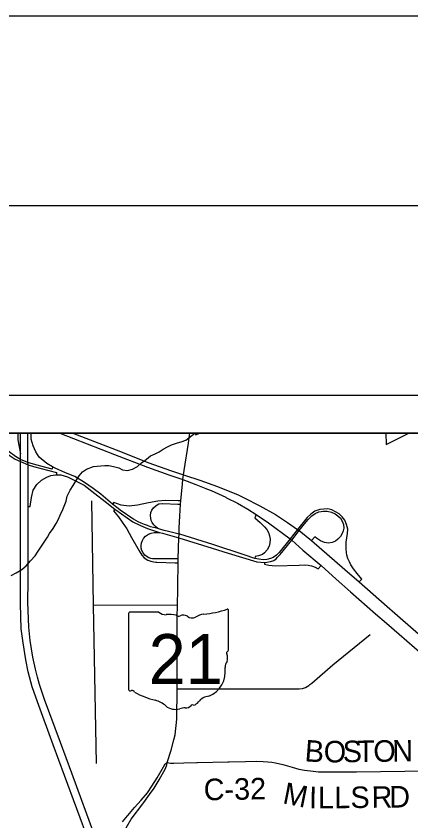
# Model space of a CAD drawing. Extents: x 0 to 34, y 0 to 22.
# Drawn here: x 5.797 to 6.839, y 19.877 to 22 of the extents above; entities that cross this region are included whole.
import ezdxf

# ---------------------------------------------------------------- set-up
doc = ezdxf.new("R2010")
doc.units = 0
for name, color, linetype in [('Default', 7, 'Continuous'), ('GM_X_City_Street', 7, 'Continuous'), ('GM_X_County_Road', 7, 'Continuous'), ('GM_X_County_Road_Text', 7, 'Continuous'), ('GM_X_Interchange_Ramps', 7, 'Continuous'), ('GM_X_Interstate_Route', 7, 'Continuous'), ('GM_X_Minor_Lake', 7, 'Continuous'), ('GM_X_Minor_River', 7, 'Continuous'), ('GM_X_State_Location', 7, 'Continuous'), ('GM_X_State_Route', 7, 'Continuous'), ('GM_X_State_Shield', 7, 'Continuous'), ('GM_X_Township_Road', 7, 'Continuous'), ('SH_Border', 7, 'Continuous'), ('SH_Cut_Line', 7, 'Continuous'), ('SH_Data', 7, 'Continuous')]:
    doc.layers.add(name, color=color, linetype=linetype)

msp = doc.modelspace()

# ---------------------------------------------------------------- linework, layer by layer
at = {"layer": 'Default'}
msp.add_lwpolyline([(8.1995, 19.7718), (8.1859, 20.3892), (8.1749, 20.9), (3.2826, 20.9)], dxfattribs=at)
msp.add_lwpolyline([(6.8332, 20.9), (6.7731, 20.9), (6.7737, 20.8697)], close=True, dxfattribs=at)
at = {"layer": 'GM_X_City_Street'}
for p, q in [((6.0008, 20.4462), (6.223, 20.4468)), ((6.2222, 20.2253), (6.544, 20.2251))]:
    msp.add_line(p, q, dxfattribs=at)
msp.add_lwpolyline([(6.0091, 20.0283), (6.0008, 20.4462), (5.9962, 20.7215)], dxfattribs=at)
at = {"layer": 'GM_X_County_Road'}
msp.add_line((6.2757, 20.0315), (6.3555, 20.0328), dxfattribs=at)
for points in [[(6.1954, 20.031), (6.2047, 20.0297), (6.2128, 20.0292), (6.2396, 20.03), (6.2737, 20.0314), (6.2757, 20.0315)], [(6.3555, 20.0328), (6.3595, 20.0329), (6.4022, 20.0334), (6.4308, 20.0346), (6.4486, 20.0337), (6.4612, 20.0332), (6.4715, 20.0323), (6.4818, 20.0306), (6.501, 20.026), (6.5259, 20.0186), (6.5436, 20.0137), (6.5579, 20.0111), (6.5739, 20.0088), (6.5954, 20.0068), (6.6229, 20.0068), (6.6953, 20.0065), (6.8865, 20.0091)]]:
    msp.add_lwpolyline(points, dxfattribs=at)
at = {"layer": 'GM_X_Interchange_Ramps'}
msp.add_line((6.4272, 20.5695), (6.3989, 20.5788), dxfattribs=at)
for points in [[(5.7276, 20.9), (5.7296, 20.896), (5.7412, 20.8797), (5.7522, 20.8668), (5.7633, 20.8541), (5.7783, 20.842), (5.7944, 20.8312), (5.8083, 20.8248), (5.8283, 20.8162), (5.8428, 20.812), (5.9033, 20.7962), (5.9031, 20.7899)], [(5.8932, 20.8115), (5.8922, 20.8053), (5.8484, 20.8165), (5.8279, 20.8226), (5.8083, 20.8307), (5.7948, 20.8379), (5.7782, 20.8508), (5.7633, 20.8623), (5.749, 20.8783), (5.7368, 20.8942), (5.7337, 20.9)], [(5.8013, 20.9), (5.8016, 20.8821), (5.8082, 20.8456)], [(5.8932, 20.8115), (5.8775, 20.8202), (5.8577, 20.8362), (5.8486, 20.8509), (5.8417, 20.8664), (5.8367, 20.8841), (5.8361, 20.8976), (5.836, 20.9)], [(6.0514, 20.7129), (6.0205, 20.7386), (6.0002, 20.7537), (5.9777, 20.7701), (5.9518, 20.7853), (5.9268, 20.7956), (5.9, 20.8077), (5.8932, 20.8115)], [(5.8282, 20.7064), (5.8335, 20.7066), (5.8369, 20.7304), (5.8417, 20.7494), (5.8512, 20.7641), (5.8637, 20.7762), (5.878, 20.7835), (5.8888, 20.7883), (5.9009, 20.79), (5.9031, 20.7899)], [(5.9031, 20.7899), (5.9147, 20.7896), (5.9328, 20.7848), (5.9549, 20.7736), (5.9764, 20.7628), (6.0045, 20.7408), (6.0318, 20.72), (6.0573, 20.6994), (6.0598, 20.6974), (6.1049, 20.6663), (6.1249, 20.6559), (6.1439, 20.648), (6.1646, 20.6414), (6.1754, 20.6381)], [(6.2314, 20.7211), (6.2246, 20.7212), (6.1907, 20.7222), (6.1706, 20.7207), (6.146, 20.7157), (6.1174, 20.7096), (6.0948, 20.7071), (6.0737, 20.7096), (6.0546, 20.7172), (6.0514, 20.7129)], [(6.1713, 20.6483), (6.164, 20.6499), (6.1591, 20.6511), (6.1516, 20.6532), (6.1438, 20.6563), (6.1358, 20.6593), (6.1273, 20.6628), (6.1191, 20.6664), (6.1128, 20.6699), (6.107, 20.6734), (6.094, 20.6812), (6.0843, 20.6877), (6.0746, 20.6944), (6.0626, 20.7037), (6.0514, 20.7129)], [(6.0573, 20.6994), (6.054, 20.695), (6.0667, 20.679), (6.0771, 20.6652), (6.0886, 20.6474), (6.1016, 20.6247), (6.1213, 20.5898), (6.1284, 20.5782), (6.1347, 20.5708), (6.1447, 20.5648), (6.1552, 20.5611), (6.166, 20.5599)], [(6.1713, 20.6483), (6.165, 20.6539), (6.1604, 20.6584), (6.1563, 20.6638), (6.1535, 20.6693), (6.1522, 20.6754), (6.1515, 20.6824), (6.1528, 20.6905), (6.1551, 20.6972), (6.1597, 20.7033), (6.1663, 20.7087), (6.1735, 20.7131), (6.1834, 20.7145)], [(6.1834, 20.7145), (6.1845, 20.7146), (6.224, 20.7129), (6.2309, 20.7126)], [(6.7028, 20.5075), (6.7097, 20.5152), (6.6968, 20.5301), (6.6871, 20.542), (6.6806, 20.5522), (6.6766, 20.5607), (6.6724, 20.5695), (6.6703, 20.5782), (6.6689, 20.5849), (6.6685, 20.5943), (6.6679, 20.6127), (6.6715, 20.6348), (6.6723, 20.6466), (6.6694, 20.659), (6.6644, 20.6708), (6.6574, 20.679), (6.6498, 20.6867), (6.6402, 20.6928), (6.6301, 20.6977), (6.6193, 20.6999), (6.6094, 20.6997), (6.5987, 20.6982), (6.5854, 20.694), (6.5748, 20.6865), (6.5652, 20.6773), (6.5399, 20.6457), (6.5201, 20.621), (6.4912, 20.585), (6.484, 20.5782), (6.4752, 20.5722), (6.4684, 20.5692), (6.4584, 20.5667), (6.4489, 20.5661), (6.4374, 20.5674), (6.4272, 20.5695)], [(6.4309, 20.6857), (6.4267, 20.6765), (6.4413, 20.6646), (6.4529, 20.6529), (6.4588, 20.6454), (6.4633, 20.6377), (6.4661, 20.6293), (6.4671, 20.6206), (6.4666, 20.6104), (6.4645, 20.6015), (6.4592, 20.5917), (6.4522, 20.5841), (6.4469, 20.58), (6.4366, 20.5759), (6.4279, 20.5743), (6.4272, 20.5695)], [(6.4525, 20.5585), (6.4587, 20.5592), (6.4681, 20.5613), (6.4768, 20.5644), (6.4829, 20.5683), (6.4869, 20.5726), (6.4941, 20.5797), (6.5243, 20.6177), (6.5441, 20.6427), (6.5581, 20.6603), (6.5677, 20.672), (6.5774, 20.6816), (6.5862, 20.6879), (6.596, 20.6921), (6.608, 20.6939), (6.6183, 20.6941), (6.6294, 20.6914), (6.6389, 20.6868), (6.6463, 20.6816), (6.6528, 20.6753), (6.6577, 20.6679), (6.6611, 20.6587), (6.6617, 20.6494), (6.6605, 20.6422), (6.6579, 20.6356), (6.6533, 20.6275), (6.6463, 20.6201), (6.6396, 20.6151), (6.6311, 20.6115), (6.6211, 20.6098), (6.6105, 20.6119), (6.6005, 20.616), (6.5902, 20.6226), (6.5856, 20.6262), (6.5767, 20.6164)], [(6.2247, 20.5683), (6.2167, 20.5686), (6.1566, 20.5682), (6.1526, 20.5691), (6.1475, 20.571), (6.1429, 20.5739), (6.1367, 20.5785), (6.1324, 20.5841), (6.129, 20.5903), (6.1271, 20.5966), (6.1268, 20.6027), (6.1276, 20.6104), (6.1302, 20.6164), (6.1328, 20.6219), (6.1381, 20.6278), (6.1462, 20.6333), (6.1533, 20.6362), (6.1613, 20.6375), (6.1678, 20.6381), (6.1754, 20.6381)], [(6.2287, 20.6331), (6.2268, 20.6337), (6.1993, 20.6404), (6.1878, 20.6432), (6.1791, 20.6455), (6.1713, 20.6483)], [(6.1754, 20.6381), (6.183, 20.6358), (6.2264, 20.6238), (6.314, 20.5961), (6.3562, 20.5835)], [(6.3989, 20.5788), (6.3161, 20.6061), (6.2287, 20.6331)], [(6.3562, 20.5835), (6.432, 20.5608), (6.4525, 20.5585)], [(6.166, 20.5599), (6.1682, 20.5596), (6.2165, 20.5581), (6.2244, 20.5581)], [(6.4525, 20.5585), (6.4522, 20.5541), (6.464, 20.5518), (6.4812, 20.5503), (6.5443, 20.552), (6.5577, 20.5523), (6.5678, 20.5514), (6.5769, 20.5495), (6.5862, 20.5465), (6.5945, 20.5422), (6.6018, 20.5504)]]:
    msp.add_lwpolyline(points, dxfattribs=at)
at = {"layer": 'GM_X_Interstate_Route'}
for points in [[(5.9892, 19.821), (5.9247, 19.9966), (5.8947, 20.0779), (5.8532, 20.1908), (5.8395, 20.2305), (5.8289, 20.2705), (5.8221, 20.3024), (5.8153, 20.3469), (5.8104, 20.3837), (5.8083, 20.45), (5.8081, 20.5587), (5.8083, 20.8248), (5.8083, 20.8307), (5.8082, 20.8456), (5.8081, 20.9)], [(5.8281, 20.5097), (5.8285, 20.5596), (5.8282, 20.7064), (5.8288, 20.7539), (5.8283, 20.8162), (5.8279, 20.8226), (5.8274, 20.9)], [(5.9125, 20.9), (6.0567, 20.8439), (6.1434, 20.8102), (6.2002, 20.7897), (6.2128, 20.7855)], [(5.9463, 20.9), (6.0606, 20.8558), (6.1473, 20.822), (6.2042, 20.8015), (6.2389, 20.7901), (6.241, 20.7894), (6.2822, 20.7759), (6.3288, 20.7588), (6.3746, 20.7403)], [(6.2128, 20.7855), (6.2371, 20.7775), (6.2715, 20.7649), (6.2978, 20.754)], [(6.2978, 20.754), (6.2997, 20.7532), (6.3115, 20.7483), (6.35, 20.731), (6.3526, 20.7296)], [(6.3526, 20.7296), (6.3815, 20.7149), (6.4084, 20.6994), (6.4309, 20.6857), (6.4631, 20.6636), (6.5201, 20.621), (6.5243, 20.6177), (6.5539, 20.5915), (6.6018, 20.5504)], [(6.3746, 20.7403), (6.381, 20.7377), (6.3988, 20.7289), (6.4404, 20.7086), (6.4813, 20.685), (6.5132, 20.6642), (6.5399, 20.6457), (6.5441, 20.6427), (6.5767, 20.6164)], [(6.5767, 20.6164), (6.6649, 20.5406), (6.7028, 20.5075)], [(6.6018, 20.5504), (6.6418, 20.5144), (6.6797, 20.4812), (6.7455, 20.4236), (6.7749, 20.3983)], [(5.8532, 20.256), (5.8477, 20.277), (5.8409, 20.3088), (5.834, 20.3533), (5.8304, 20.388), (5.8276, 20.4538), (5.8281, 20.5097)], [(6.7028, 20.5075), (6.7765, 20.4427), (6.7966, 20.4252)], [(6.7966, 20.4252), (6.9486, 20.2925), (7.156, 20.1111), (7.2785, 20.0062), (7.3237, 19.9679), (7.3987, 19.9098), (7.4761, 19.8527), (7.5666, 19.7895), (7.7006, 19.7055), (7.763, 19.6693)], [(6.7749, 20.3983), (6.8079, 20.3699), (6.8685, 20.317), (6.9085, 20.2814), (6.9964, 20.2046), (7.0553, 20.1519), (7.149, 20.0706), (7.2156, 20.0127), (7.2801, 19.959), (7.343, 19.9077), (7.4133, 19.8545), (7.4638, 19.8177), (7.5083, 19.7871), (7.5915, 19.7321), (7.6978, 19.6669), (7.77, 19.6256)], [(6.0314, 19.7661), (6.0236, 19.7873), (6.0062, 19.8324), (5.9435, 20.003), (5.9135, 20.0843), (5.8719, 20.1972), (5.8583, 20.237), (5.8532, 20.256)]]:
    msp.add_lwpolyline(points, dxfattribs=at)
at = {"layer": 'GM_X_Minor_Lake'}
for p, q in [((6.2698, 20.9), (6.2711, 20.8952)), ((6.2711, 20.8952), (6.2805, 20.9))]:
    msp.add_line(p, q, dxfattribs=at)
at = {"layer": 'GM_X_Minor_River'}
msp.add_lwpolyline([(5.7833, 20.5246), (5.7969, 20.5315), (5.8116, 20.54), (5.8236, 20.5496), (5.8349, 20.563), (5.8473, 20.576), (5.8551, 20.5886), (5.8622, 20.5989), (5.8712, 20.6123), (5.8794, 20.6256), (5.885, 20.6352), (5.8944, 20.6482), (5.9026, 20.6619), (5.9086, 20.6733), (5.9134, 20.684), (5.9197, 20.6981), (5.9238, 20.7076), (5.9286, 20.7206), (5.9319, 20.7335), (5.9398, 20.7492), (5.9469, 20.7614), (5.9551, 20.7747), (5.9629, 20.787), (5.9723, 20.798), (5.9825, 20.8046), (6.0006, 20.812), (6.0108, 20.8128), (6.0207, 20.8137), (6.0313, 20.8149), (6.0411, 20.8146), (6.054, 20.812), (6.0677, 20.808), (6.0779, 20.8035), (6.0904, 20.8017), (6.1041, 20.8045), (6.1176, 20.8118), (6.1278, 20.8214), (6.1406, 20.8314), (6.1515, 20.8398), (6.1639, 20.8456), (6.1745, 20.851), (6.1847, 20.8576), (6.1964, 20.8641), (6.2073, 20.8695), (6.2224, 20.8746), (6.2326, 20.877), (6.2447, 20.8816), (6.2689, 20.9)], dxfattribs=at)
at = {"layer": 'GM_X_State_Route'}
for points in [[(6.2407, 20.8017), (6.2515, 20.8735), (6.2546, 20.8942), (6.2555, 20.9)], [(6.2359, 20.7659), (6.2371, 20.7775), (6.2389, 20.7901), (6.2407, 20.8017)], [(6.2237, 20.4873), (6.2239, 20.4964), (6.2244, 20.5581), (6.2247, 20.5683), (6.2264, 20.6238), (6.2268, 20.6337), (6.2273, 20.6504), (6.229, 20.6813), (6.2309, 20.7126), (6.2314, 20.7211), (6.2359, 20.7659)], [(6.213, 20.091), (6.2165, 20.104), (6.2214, 20.1453), (6.2222, 20.2253), (6.2223, 20.2903), (6.2223, 20.4138), (6.223, 20.4468), (6.2237, 20.4873)], [(6.1954, 20.031), (6.2057, 20.064), (6.213, 20.091)], [(6.0904, 19.8904), (6.0913, 19.8914), (6.1095, 19.9127), (6.1267, 19.9314), (6.1435, 19.9516), (6.1554, 19.9685), (6.1692, 19.9903), (6.1855, 20.02), (6.1899, 20.0281), (6.1954, 20.031)], [(6.1312, 19.9225), (6.1335, 19.9256), (6.149, 19.9466), (6.1609, 19.9635), (6.1747, 19.9854), (6.1911, 20.015), (6.1946, 20.0252), (6.1954, 20.031)], [(6.0764, 19.6759), (6.0754, 19.6808), (6.0686, 19.7195), (6.0651, 19.7366), (6.0641, 19.763), (6.0672, 19.7966), (6.0733, 19.8251), (6.0869, 19.859), (6.1007, 19.8817), (6.1312, 19.9225)], [(6.0772, 19.8747), (6.0904, 19.8904)]]:
    msp.add_lwpolyline(points, dxfattribs=at)
at = {"layer": 'GM_X_State_Shield'}
for p, q in [((6.0938, 20.4241), (6.0938, 20.2239)), ((6.1736, 20.4275), (6.0964, 20.4275)), ((6.3575, 20.3278), (6.3575, 20.4325)), ((6.3574, 20.3278), (6.3575, 20.3278))]:
    msp.add_line(p, q, dxfattribs=at)
for centre, radius, start, end in [((6.0968, 20.4245), 0.00305, 98.1301, 188.1301), ((6.192, 20.4507), 0.0296, 231.6195, 271.1119), ((6.2992, 20.3664), 0.0563, 97.3462, 120.7689), ((6.2635, 20.7003), 0.2796, 275.8445, 288.9065), ((6.3545, 20.4329), 0.00294, 351.8621, 97.738), ((6.2018, 20.3152), 0.1064, 80.4867, 94.9883), ((6.226, 20.4255), 0.00855, 219.7921, 297.1024), ((6.2385, 20.4024), 0.0178, 54.4667, 119.1411), ((6.2614, 20.4341), 0.0214, 233.8562, 294.8282), ((6.3568, 20.3201), 0.00454, 107.944, 210.337), ((6.3279, 20.3069), 0.0273, 340.033, 23.6496), ((6.3543, 20.3274), 0.00314, 289.6038, 7.7341), ((6.368, 20.284), 0.0198, 136.8065, 186.9296), ((6.2792, 20.2707), 0.0699, 292.3089, 8.9858), ((6.0968, 20.2235), 0.00308, 171.9584, 258.3066), ((6.0973, 20.244), 0.0235, 267.339, 280.6039), ((6.1021, 20.2124), 0.00848, 29.7484, 93.2717), ((6.2092, 20.3922), 0.2019, 240.4129, 257.1985), ((6.149, 20.134), 0.0632, 47.1842, 75.836), ((6.2602, 20.2045), 0.0226, 282.8732, 323.2771), ((6.3087, 20.1678), 0.0383, 94.4031, 142.5768), ((6.2173, 20.2114), 0.0401, 230.7004, 286.2918), ((6.2405, 20.1422), 0.0329, 85.6951, 111.2099), ((6.2434, 20.1964), 0.0214, 268.777, 315.5493), ((6.2627, 20.177), 0.00601, 65.7517, 132.6484)]:
    msp.add_arc(centre, radius, start, end, dxfattribs=at)
at = {"layer": 'GM_X_Township_Road'}
for points in [[(6.5722, 20.2366), (6.5772, 20.2406), (6.6332, 20.2887), (6.7314, 20.3686)], [(6.544, 20.2251), (6.553, 20.2267), (6.5606, 20.2294), (6.5697, 20.2345), (6.5722, 20.2366)]]:
    msp.add_lwpolyline(points, dxfattribs=at)
at = {"layer": 'SH_Border'}
msp.add_lwpolyline([(1.5, 21.5), (33.5, 21.5), (33.5, 0.5), (1.5, 0.5)], close=True, dxfattribs=at)
at = {"layer": 'SH_Cut_Line'}
for points in [[(0, 0), (34, 0), (34, 22), (0, 22)], [(3.2807, 14.1), (8.9, 14.1), (8.9, 20.9), (3.2826, 20.9), (3.2843, 20.6124), (3.2845, 20.5998), (3.2888, 19.8918), (3.2901, 19.68), (3.2904, 19.1173), (3.2907, 18.4315), (3.2837, 17.3796), (3.2835, 17.0107), (3.2832, 16.3898), (3.2829, 15.8433), (3.2815, 15.7537), (3.2811, 15.7294), (3.2832, 14.8896), (3.2841, 14.501), (3.2822, 14.2781), (3.2808, 14.1155)]]:
    msp.add_lwpolyline(points, close=True, dxfattribs=at)
at = {"layer": 'SH_Data'}
for p, q in [((2, 21), (9, 21)), ((2.1, 20.9), (8.9, 20.9))]:
    msp.add_line(p, q, dxfattribs=at)

# ---------------------------------------------------------------- texts
at = {"layer": 'GM_X_County_Road_Text'}
for s, height, rotation, p in [('B', 0.0568, 355.7028, (6.5573, 20.0346)), ('O', 0.0568, 0.8167, (6.6094, 20.031)), ('S', 0.0568, 0.7317, (6.6594, 20.0317)), ('T', 0.0568, 0.7388, (6.6977, 20.0322)), ('O', 0.0568, 0.7322, (6.7402, 20.0327)), ('N', 0.0568, 0.736, (6.7902, 20.0333)), ('C-32', 0.05682, 1.0158, (6.2925, 19.9313)), ('M', 0.0568, 348.6941, (6.4981, 19.9239)), ('I', 0.0568, 359.3476, (6.57, 19.9106)), ('L', 0.0568, 0.0575, (6.5941, 19.9104)), ('L', 0.0568, 0.5863, (6.6372, 19.9104)), ('S', 0.0568, 0.71, (6.6798, 19.9108)), ('R', 0.0568, 0.726, (6.7356, 19.9115)), ('D', 0.0568, 0.7303, (6.7823, 19.9121))]:
    msp.add_text(s, height=height, rotation=rotation, dxfattribs=at).set_placement(p)
at = {"layer": 'GM_X_State_Location'}
msp.add_text('21', height=0.000189, rotation=0, dxfattribs=at).set_placement((6.175, 20.2969))
for s, p in [('s', (6.2227, 20.3107)), ('r', (6.2226, 20.3107))]:
    msp.add_text(s, height=0.000189, dxfattribs=at).set_placement(p)
at = {"layer": 'GM_X_State_Shield'}
msp.add_text('21', height=0.13184, dxfattribs=at).set_placement((6.1465, 20.2381))

doc.saveas('drawing.dxf')
